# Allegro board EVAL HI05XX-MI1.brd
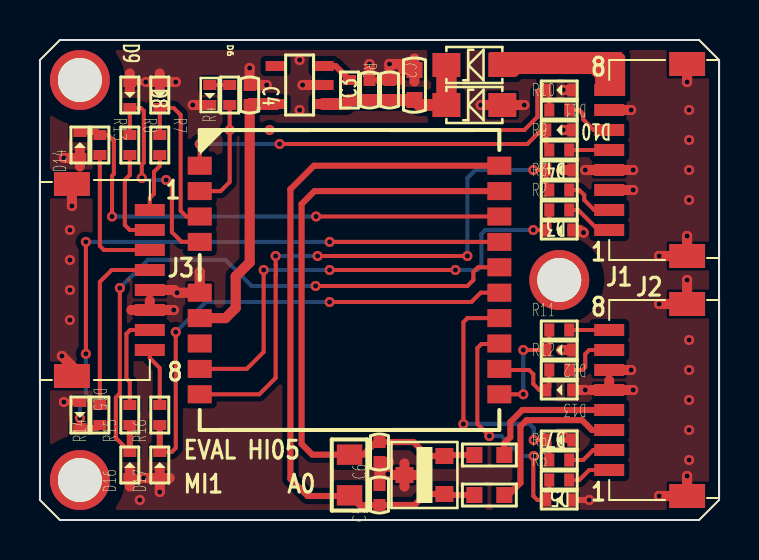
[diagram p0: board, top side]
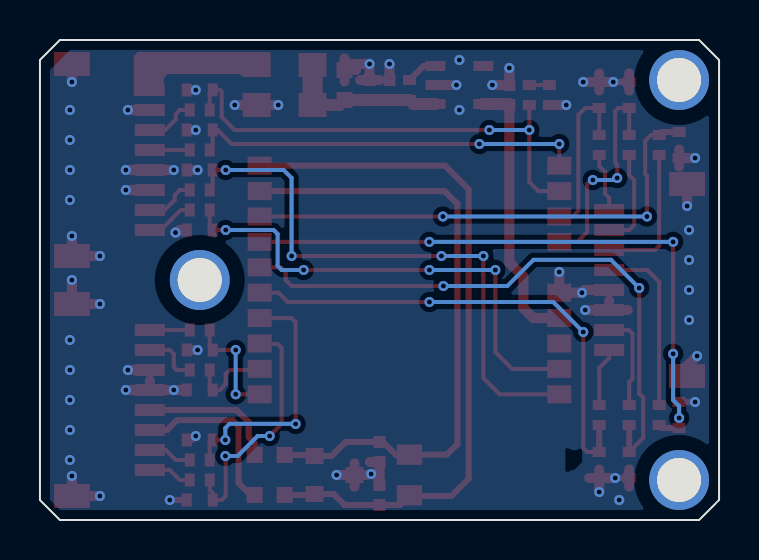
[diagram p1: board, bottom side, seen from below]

Outline 34 x 24 mm; copper layers: TOP, BOTTOM. Coordinates in mm from the lower left corner of the outline.
Outline path: 0,23 0,1 1,0 33,0 34,1 34,23 33,24 1,24 0,23

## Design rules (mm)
constraint set DEFAULT: min track width 0.203
net group CAN2: nets H L

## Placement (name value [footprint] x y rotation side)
C1  10uF  [C0603]  18.75 21.75 270 top
C2  0.1uF  [C0402]  17.5 21.5 270 top
C3  1uF  [C0402]  16.5 21.5 90 top
C4  1uF  [C0402]  10.5 21.25 270 top
C5  100pF  [C0402]  17 1.25 90 top
C6  100pF  [C0402]  17 3.4 90 top
D1  1N5819  [SOD123FL]  21.75 22.75 0 top
D2  SDD32A05L01  [SOD123FL]  21.75 20.75 0 top
D3  SBD52C05L01  [SOD-523]  26 14.5 180 top
D4  SBD52C05L01  [SOD-523]  26 17.5 180 top
D5  SBD52C05L01  [SOD-523]  26 1 180 top
D6  GREEN  [LED0402]  8.5 21.25 270 top
D7  SBD52C05L01  [SOD-523]  26 4 180 top
D8  SBD52C05L01  [SOD-523]  6 21.25 270 top
D9  SBD52C05L01  [SOD-523]  4.5 21.25 270 top
D10  SBD52C05L01  [SOD-523]  26 19.5 180 top
D11  SBD52C05L01  [SOD-523]  26 21.5 180 top
D12  SBD52C05L01  [SOD-523]  26 8.5 180 top
D13  SBD52C05L01  [SOD-523]  26 6.5 180 top
D14  SBD52C05L01  [SOD-523]  2 18.75 90 top
D15  SBD52C05L01  [SOD-523]  2 5.25 270 top
D16  SBD52C05L01  [SOD-523]  4.5 2.75 90 top
D17  SBD52C05L01  [SOD-523]  6 2.75 90 top
D18  SM24CANB-02HTG  [SOT23-3-0_95]  19.25 2.25 90 top
F1  100mA  [F0603]  22.5 1.25 180 top
F2  100mA  [F0603]  22.5 3.25 180 top
H1  HOLE  [HOLE-2-MM]  2 22 0 top
H2  HOLE  [HOLE-2-MM]  2 2 0 top
H3  HOLE  [HOLE-2-MM]  26 12 0 top
J1  CON10  [5015680807_1]  28.5 18 270 top
J2  CON10  [5015680807_1]  28.5 6 270 top
J3  CON10  [5015680807_1]  5.5 12 90 top
R1  1K  [R0402]  15.5 21.5 270 top
R2  33R  [R0402]  26 15.5 0 top
R3  33R  [R0402]  26 16.5 0 top
R4  510R  [R0402]  9.5 21.25 90 top
R5  33R  [R0402]  26 2 0 top
R6  33R  [R0402]  26 3 0 top
R7  33R  [R0402]  6 18.75 270 top
R8  33R  [R0402]  4.5 18.75 270 top
R9  33R  [R0402]  26 18.5 0 top
R10  33R  [R0402]  26 20.5 0 top
R11  33R  [R0402]  26 9.5 0 top
R12  33R  [R0402]  26 7.5 0 top
R13  33R  [R0402]  3 18.75 270 top
R14  33R  [R0402]  3 5.25 90 top
R15  33R  [R0402]  4.5 5.25 90 top
R16  33R  [R0402]  6 5.25 90 top
R17  120R/DNP  [R0805]  15.5 2.25 270 top
U1  SPX3819M5-L-3-3/TR  [SOT23-5-0_95]  13 21.75 90 top
U2  HI05XX-MI1  [HI02_HI05]  15.5 12 0 top

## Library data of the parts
C1-C6 = Capacity_Nonpolarity
D1 = diode
D2-D5 D7-D17 = DIODE BI-DIR TRIG
D6 = LED
D18 = BAT54A/SOT
F1 F2 = Fuse
H1-H3 = HOLE
J1-J3 = CON10
R1-R17 = Res
U1 = XC6210
U2 = HI05XX-MI1

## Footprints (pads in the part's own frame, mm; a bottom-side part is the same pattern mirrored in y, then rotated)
5015680807_1
  rect 0.6x1.5 smd: 1(3.5,0) 2(2.5,0) 3(1.5,0) 4(0.5,0) 5(-0.5,0) 6(-1.5,0) 7(-2.5,0) 8(-3.5,0)
  rect 1.2x1.8 smd: 9(4.8,3.9) 10(-4.8,3.9)
C0402
  rect 0.6x0.6 smd: 1(-0.5,0) 2(0.5,0)
C0603
  rect 0.8x0.8 smd: 1(-0.75,0) 2(0.75,0)
F0603
  rect 0.8x0.8 smd: 1(-0.75,0) 2(0.75,0)
HI02_HI05
  rect 1.2x0.9 smd: 1(-7.5,5.715) 2(-7.5,4.445) 3(-7.5,3.175) 4(-7.5,1.905) 5(-7.5,-0.635) 6(-7.5,-1.905) 7(-7.5,-3.175) 8(-7.5,-4.445) 9(-7.5,-5.715) 10(7.5,-5.715) 11(7.5,-4.445) 12(7.5,-3.175) 13(7.5,-1.905) 14(7.5,-0.635) 15(7.5,0.635) 16(7.5,1.905) 17(7.5,3.175) 18(7.5,4.445) 19(7.5,5.715)
HOLE-2-MM
  round 3 hole 2.2: 1(0,0)
LED0402
  rect 0.5x0.65 smd: 1(-0.5,0) 2(0.5,0)
R0402
  rect 0.5x0.65 smd: 1(-0.5,0) 2(0.5,0)
R0805
  rect 1.016x1.27 smd: 1(-1.016,0) 2(1.016,0)
SOD123FL
  rect 1.4x1.2 smd: 1(1.4,0) 2(-1.4,0)
SOD-523
  rect 0.5x0.65 smd: 1(-0.65,0) 2(0.65,0)
SOT23-3-0_95
  rect 0.8x0.9 smd: 1(-0.95,-1) 2(0.95,-1) 3(0,1)
SOT23-5-0_95
  rect 0.5x1 smd: 1(-0.95,-1.2) 2(0,-1.2) 3(0.95,-1.2) 4(0.95,1.2) 5(-0.95,1.2)

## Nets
5V: D1.1(P) J1.8
GND: C1.1 C2.1 C3.2 C4.1 C5.2 C6.1 D2.1 D3.1 D4.1 D5.1 D6.2(-) D7.1 D8.1 D9.1 D10.1 D11.1 D12.1 D13.1 D14.1 D15.1 D16.1 D17.1 D18.3 J1.3 J1.4 J1.7 J1.9 J1.10 J2.5 J2.6 J2.9 J2.10 J3.5 J3.6 J3.9 J3.10 U1.2(VSS) U2.5
VCC: C1.2 C2.2 C3.1 D1.2 D2.2 R1.2 U1.1
CAN_H: C5.1 D18.1 F1.2 R17.2 U2.19
CAN_L: C6.2 D18.2 F2.2 R17.1 U2.18
CS: D17.2 R16.1 U2.14
DP3V3: C4.2 U1.5 U2.6(VDD)
H: F1.1 J2.3
L: F2.1 J2.4
MISO: D15.2 R14.1 U2.16
MOSI: D14.2 R13.1 U2.17
RXD1: D4.2 R3.1 U2.9
RXD2: D7.2 R6.1 U2.13
RXD3/SDA2: D13.2 R12.1 U2.11
RXD4: D9.2 R8.1 U2.4
SCK: D16.2 R15.1 U2.15
SIN/PPS: J1.5 R9.2
SOUT: J1.6 R10.2
SPI_CS: J3.8 R16.2
SPI_MISO: J3.4 R14.2
SPI_MOSI: J3.3 R13.2
SPI_SCK: J3.7 R15.2
SYNC_IN/PPS: D10.2 R9.1 U2.1
SYNC_OUT: D11.2 R4.1 R10.1 U2.2
TXD1: D3.2 R2.1 U2.8
TXD2: D5.2 R5.1 U2.12
TXD3/SCL2: D12.2 R11.1 U2.10
TXD4: D8.2 R7.1 U2.3
USART1_RX: J1.2 R3.2
USART1_TX: J1.1 R2.2
USART2_RX: J2.2 R6.2
USART2_TX: J2.1 R5.2
USART3_RX: J2.7 R12.2
USART3_TX: J2.8 R11.2
USART4_RX: J3.2 R8.2
USART4_TX: J3.1 R7.2
N2198535: D6.1 R4.2
N2224750: R1.1 U1.3

Pads without a net: H1 1; H2 1; H3 1; U1 4; U2 7

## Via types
v1: diameter 0.508, hole 0.254, TOP to BOTTOM, 88 vias

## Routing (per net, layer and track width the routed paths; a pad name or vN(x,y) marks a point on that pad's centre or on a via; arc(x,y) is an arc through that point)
GND: length 56.1
  TOP w0.305: D15.1 v1(1.2,5.9) ; D7.1 26.4,4 v1(26.2,4.2) ; D5.1 v1(27.5,1) ; D16.1 v1(5.2,2.1) ; D9.1 v1(5.29,21.9)
  TOP w0.5: 5.5,10.98 J3.6 4.57,10.5 ; 18.25,1.67 D18.3 ; D18.3 18.25,2.83 ; D18.3 17.62,2.25 ; 6,21.47 D8.1 ; D8.1 5.5,21.9 ; D8.1 6,22.33 ; 4.5,2.53 D16.1 4.5,1.67 ; 2,17.67 D14.1 2,18.53 ; 17.02,22 C2.1 17.98,22 ; 4.5,22.33 D9.1 4.5,21.47 ; 18.17,22.5 C1.1 ; C1.1 18.75,21.92 ; C1.1 18.75,23.08 ; 17,2.42 C6.1 17.48,2.9 ; 6.5,2.1 D17.1 6,2.53 ; 28.5,6.98 J2.5 27.57,6.5
  TOP w0.508: v1(27.21,14.37) 27.18,14.4 27.1,14.4 27,14.5 D3.1 ; D6.2 v1(7.65,20.75) ; D11.1 v1(26.2,21.5) ; v1(32.4,2.2) J2.9 v1(31,1.2) ; J1.3 v1(29.7,16.5) ; D18.3 v1(19.15,2.25) ; C3.2 v1(16.5,22.8) ; v1(22.07,20.75) D2.1 v1(24.25,20.75) ; v1(31,13.2) J1.9 v1(32.4,14.2) ; v1(32.4,12) J2.10 v1(31,10.8) ; v1(10.5,22.6) C4.1 v1(11.35,21.75) ; J2.6 v1(29.6,7.5) ; v1(1.1,8.2) 1.6,7.7 J3.10 ; J3.9 v1(1.6,15.7) ; J3.6 v1(6.7,10.5) ; J2.5 v1(29.7,6.5) ; v1(29.7,17.5) J1.4 v1(27.3,17.5) ; J3.5 6.73,11.5 v1(6.86,11.37) U2.5 v1(8,12.4) ; D12.1 v1(26.11,8.5) ; C1.1 18.45,22.8 v1(17.5,22.8) C2.1 ; J1.10 v1(32.4,21.9) ; D14.1 v1(1.2,18.1) ; D10.1 v1(26.2,19.5) ; J1.7 v1(29.6,20.5) ; D4.1 v1(26.11,17.5) ; D8.1 v1(6.8,21.9) ; v1(17.42,2.3) 17,2.3 C5.2 ; v1(5.2,2.1) D17.1 v1(6,1.4) ; D13.1 v1(27.3,6.5) ; U1.2 v1(13.15,21.75)
  vias: v1(1.5,14.5) v1(1.5,13) v1(1.5,11.5) v1(1.5,10) v1(5,1) v1(13,23) v1(13,20.5) v1(32.5,20.5) v1(32.5,19) v1(32.5,17.5) v1(32.5,16) v1(32.5,9) v1(32.5,7.5) v1(32.5,6) v1(32.5,4.5) v1(32.5,3)
VCC: length 8.3
  TOP w0.6: U1.1 15.3,20.8 R1.2 C3.1 C2.2 C1.2 19,20.75 D2.2
  TOP w1.016: D1.2 D2.2
CAN_H: length 35.5
  TOP w0.305: F1.2 20.3,1.25 D18.1 19.3,1.3 18.75,0.75 C5.1 15.98,0.75 R17.2 15.47,1.2 13.4,1.2 12.54,2.06 12.54,16.54 13.71,17.72 U2.19
CAN_L: length 31.6
  TOP w0.305: U2.18 13.74,16.45 13.1,15.8 13.1,3.8 13.63,3.27 R17.1 16.19,3.27 16.83,3.9 C6.2 18.7,3.9 19.4,3.2 D18.2 20.3,3.25 F2.2
CS: length 25
  TOP w0.203: v1(6.8,9.4) 6.8,3.6 6.6,3.4 D17.2 ; v1(14.5,10.9) 21.6,10.9 22.06,11.37 U2.14
  TOP w0.305: R16.1 D17.2
  BOTTOM w0.203: v1(6.8,9.4) 8.3,10.9 v1(14.5,10.9)
DP3V3: length 13.8
  TOP w0.508: U2.6 9.29,10.1 9.8,10.6 9.8,12.18 10.5,12.88 C4.2
  TOP w0.6: C4.2 10.55,20.8 U1.5
H: length 8.7
  TOP w0.305: J2.3 27.63,4.5 27.14,4.99 24.36,4.99 24.06,4.69 24.06,1.85 23.45,1.25 F1.1
L: length 7
  TOP w0.305: J2.4 24.15,5.5 23.55,4.9 23.55,4.14 23.25,3.84 F2.1
MISO: length 31.3
  TOP w0.203: v1(2.3,13.91) v1(2.3,8.31) ; D15.2 v1(2,5.1) 2,5.14 2.06,5.08 ; U2.16 v1(14.51,13.91)
  TOP w0.305: D15.2 2.85,4.6 R14.1
  BOTTOM w0.203: v1(14.51,13.91) v1(2.3,13.91) ; v1(2.3,8.31) 2.3,6 2,5.7 v1(2,5.1)
MOSI: length 25.1
  TOP w0.203: U2.17 v1(13.82,15.18) ; v1(3.61,15.18) 3.61,17.21 3.7,17.3 3.7,18.96 3.41,19.25 R13.1
  TOP w0.305: R13.1 2.85,19.4 D14.2
  BOTTOM w0.203: v1(13.82,15.18) v1(3.61,15.18)
RXD1: length 28.9
  TOP w0.203: U2.9 10.98,6.29 11.8,7.1 11.8,12.24 11.81,12.25 11.81,12.75 11.8,12.76 v1(11.8,13.2) ; v1(24.7,17.5) D4.2 25.35,16.65 R3.1 ; v1(21.4,13.2) v1(13.9,13.2)
  BOTTOM w0.203: v1(13.9,13.2) v1(11.8,13.2) ; v1(24.7,17.5) 21.8,17.5 21.4,17.1 v1(21.4,13.2)
RXD2: length 12.9
  TOP w0.203: U2.13 21.4,10.1 21.2,9.89 v1(21.2,4.8) ; v1(24.72,4) D7.2 25.5,3.85 R6.1
  BOTTOM w0.203: v1(21.2,4.8) 21.21,4.81 24.51,4.81 24.72,4.6 v1(24.72,4)
RXD3/SDA2: length 4.2
  TOP w0.203: U2.11 23.05,7.5 24.49,7.5 24.7,7.29 24.7,6.8 25,6.5 D13.2 25.5,6.65 R12.1 25.44,7.56
RXD4: length 11.1
  TOP w0.203: v1(6.32,17) 6.4,17 6.61,16.79 6.61,14.39 7.09,13.91 U2.4 ; R8.1 D9.2 5.05,20.6 5.2,20.45 5.2,17.87 5.1,17.77 v1(5.1,17.1)
  BOTTOM w0.203: v1(6.32,17) 5.2,17 v1(5.1,17.1)
SCK: length 30.7
  TOP w0.203: v1(4,11.6) 4,6.33 3.8,6.13 3.8,4.1 D16.2 ; v1(13.8,11.7) 21.4,11.7 21.7,12 21.7,12.4 21.93,12.64 U2.15
  TOP w0.305: R15.1 D16.2
  BOTTOM w0.203: v1(4,11.6) 5.41,13.01 9.29,13.01 10.6,11.7 v1(13.8,11.7)
SIN/PPS: length 2
  TOP w0.203: J1.5 R9.2
SOUT: length 2.6
  TOP w0.203: J1.6 27.73,19.5 27.2,20.03 27.2,20.3 27,20.5 R10.2
SPI_CS: length 3
  TOP w0.203: R16.2 6,7.6 5.5,8.1 J3.8
SPI_MISO: length 8.9
  TOP w0.203: R14.2 3,11.91 3.59,12.5 J3.4
SPI_MOSI: length 7.1
  TOP w0.203: R13.2 3,13.7 3.2,13.5 J3.3
SPI_SCK: length 4.9
  TOP w0.203: R15.2 4.5,6.9 4.33,7.07 4.33,9.31 4.52,9.5 J3.7
SYNC_IN/PPS: length 19.8
  TOP w0.203: v1(12,18.8) 24.4,18.8 25.1,19.5 D10.2 25.35,18.65 R9.1 ; v1(8,18.8) U2.1
  BOTTOM w0.203: v1(12,18.8) v1(8,18.8)
SYNC_OUT: length 24
  TOP w0.203: R4.1 v1(9.5,19.5) 9.5,16.9 9.04,16.45 U2.2 ; v1(11.5,19.5) 24.25,19.5 24.9,20.15 24.9,21.42 24.98,21.5 D11.2 25.5,21.35 R10.1
  BOTTOM w0.203: v1(11.5,19.5) v1(9.5,19.5)
TXD1: length 24.6
  TOP w0.203: v1(24.7,14.5) D3.2 25.5,14.65 R2.1 ; v1(20.8,12.5) v1(14.5,12.5) ; v1(11.2,12.5) 11.2,8.4 10.35,7.56 U2.8
  BOTTOM w0.203: v1(14.5,12.5) v1(11.2,12.5) ; v1(24.7,14.5) 22.3,14.5 22.1,14.3 22.1,12.7 21.9,12.5 v1(20.8,12.5)
TXD2: length 12.3
  TOP w0.203: U2.12 22.97,8.8 22.1,8.8 21.9,8.6 21.9,4.8 v1(22.5,4.2) ; R5.1 25.5,1.5 25.35,1.35 D5.2 24.9,1 24.7,1.2 24.7,3.18 v1(24.72,3.2)
  BOTTOM w0.203: v1(24.72,3.2) 24.1,3.2 23.1,4.2 v1(22.5,4.2)
TXD3/SCL2: length 5.6
  TOP w0.203: R11.1 25.5,8.65 D12.2 v1(24.2,8.5) ; U2.10 v1(24.2,6.29)
  BOTTOM w0.203: v1(24.2,6.29) v1(24.2,8.5)
TXD4: length 8.4
  TOP w0.203: R7.1 D8.2 6.7,20.6 7.04,20.26 7.04,15.46 7.32,15.18 U2.3
USART1_RX: length 2.6
  TOP w0.203: J1.2 27.75,15.5 27.25,16 27.25,16.25 27,16.5 R3.2
USART1_TX: length 2.4
  TOP w0.203: J1.1 27.95,14.5 26.95,15.5 R2.2
USART2_RX: length 2.2
  TOP w0.203: J2.2 27.7,3.5 27.2,3 R6.2
USART2_TX: length 2.2
  TOP w0.203: R5.2 27,2 27.5,2.5 J2.1
USART3_RX: length 2.8
  TOP w0.203: J2.7 27.5,8.5 27.3,8.3 27.3,7.64 27.16,7.5 R12.2
USART3_TX: length 2
  TOP w0.203: J2.8 R11.2
USART4_RX: length 5
  TOP w0.203: J3.2 4.5,14.5 4.25,14.75 4.25,17 4.5,17.25 R8.2
USART4_TX: length 3
  TOP w0.203: R7.2 6,17.7 5.71,17.41 5.71,16.31 5.5,16.1 J3.1
N2198535: length 1
  TOP w0.203: D6.1 R4.2
N2224750: length 1.6
  TOP w0.305: U1.3 14.8,22.7 R1.1

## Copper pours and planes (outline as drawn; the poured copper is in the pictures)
5V on TOP (solid shape): 29.3,23.2 29.3,21.2 27.8,21.2 27.8,22.1 27.6,22.3 24,22.3 23.9,22.2 22.5,22.2 22.5,23.4 29.1,23.4
GND on TOP: 1.5,23.5 32.5,23.5 33.5,22.5 33.5,1 33,0.5 1.5,0.5 0.5,1.5 0.5,22.5 ; 21 cut-outs
GND on BOTTOM: 1.5,23.5 32.5,23.5 33.5,22.5 33.5,1 33,0.5 1.5,0.5 0.5,1.5 0.5,22.5 ; 2 cut-outs

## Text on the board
Ref Des/Silkscreen Top: 1 | J3 | 8 | EVAL HI05 | MI1 | A0 | J1 | J2
User.8: FIGURE | FINISHED_SIZE | 10.0 | 12.0 | 20.0 | 86.614 | DRILL CHART: TOP to BOTTOM | ALL UNITS ARE IN MILS | PLATED | QTY | 126 | 2 | 3
